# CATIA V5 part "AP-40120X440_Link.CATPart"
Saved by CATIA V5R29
Part number: AP-40120X440_Link
Source: Unknown
Bounding box of the stored display mesh (mm): x -220 to 220, y -60 to 60, z -20 to 20
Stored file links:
  C:\가치같이\SmartFactory_BoxErectorConveyor\Boxing(under)\AP-40120X440_Link.CATPart
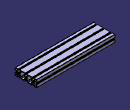
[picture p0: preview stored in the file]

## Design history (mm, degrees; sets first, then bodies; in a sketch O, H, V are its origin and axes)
Body1 (main body)
  Solid1 "PartBody": solid without history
